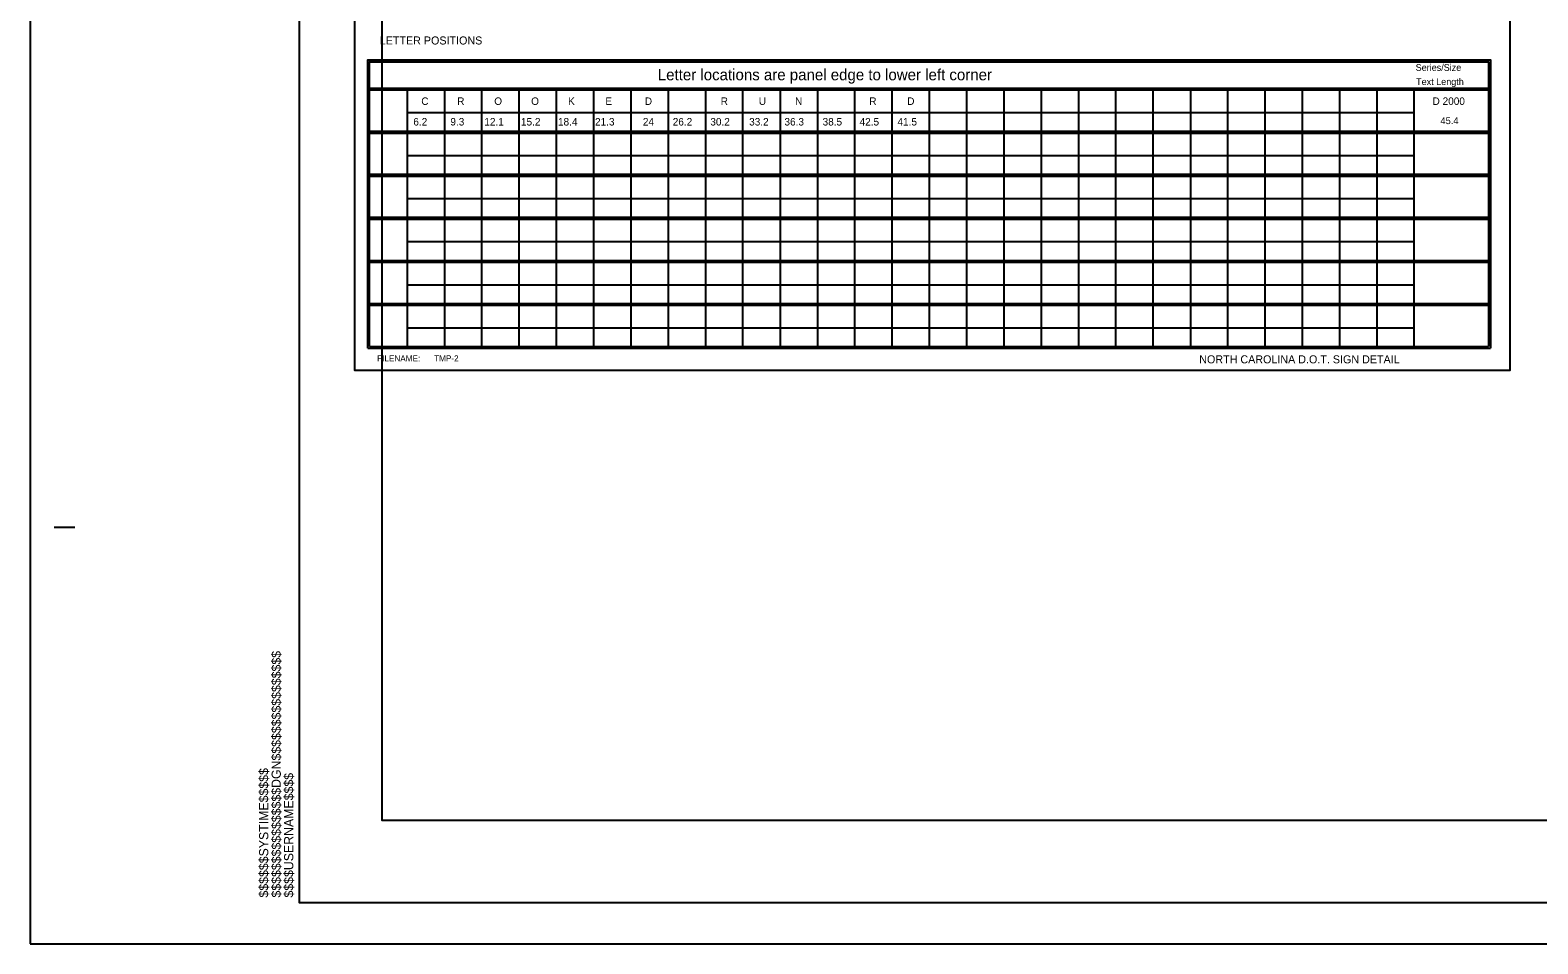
# Model space of a CAD drawing. Extents: x 766449 to 768137, y 650958 to 652521.
# Drawn here: x 766449 to 767363, y 651421 to 651975 of the extents above; entities that cross this region are included whole.
import ezdxf

# ---------------------------------------------------------------- set-up
doc = ezdxf.new("R2010")
doc.units = 0
for name, color, linetype in [('DEV BORDER CELL', 7, 'Continuous'), ('Scratch_Level_0', 7, 'Continuous'), ('Sheet Plot Border Outside CELL', 7, 'Continuous'), ('Text', 7, 'Continuous')]:
    doc.layers.add(name, color=color, linetype=linetype)

msp = doc.modelspace()

# ---------------------------------------------------------------- linework, layer by layer
at = {"layer": 'DEV BORDER CELL'}
for p, q in [((766463.84, 651673.78), (766476.34, 651673.78)), ((766612.34, 651446.28), (766612.34, 651446.28))]:
    msp.add_line(p, q, dxfattribs=at)
msp.add_lwpolyline([(768112.34, 652496.28), (766612.34, 652496.28), (766612.34, 651446.28), (768112.34, 651446.28)], close=True, dxfattribs=at)
at = {"layer": 'Scratch_Level_0'}
msp.add_lwpolyline([(768062.34, 652446.28), (766662.34, 652446.28), (766662.34, 651496.28), (767541.19, 651496.28), (767541.19, 651614.55), (768062.34, 651614.55)], close=True, dxfattribs=at)
at = {"layer": 'Sheet Plot Border Outside CELL'}
msp.add_lwpolyline([(766449.34, 651421.28), (768137.34, 651421.28), (768137.34, 652521.28), (766449.34, 652521.28)], close=True, dxfattribs=at)
at = {"layer": 'Text'}
for p, q in [((766655.01, 651940.06), (767193.2, 651940.06)), ((766655.01, 651938.93), (767193.2, 651938.93)), ((766677.71, 651938.93), (766677.71, 651913.95)), ((766700.4, 651938.93), (766700.4, 651913.95)), ((766722.86, 651938.93), (766722.86, 651913.95)), ((766745.55, 651938.93), (766745.55, 651913.95)), ((766768.01, 651938.93), (766768.01, 651913.95)), ((766790.71, 651938.93), (766790.71, 651913.95)), ((766813.4, 651938.93), (766813.4, 651913.95)), ((766835.86, 651938.93), (766835.86, 651913.95)), ((766858.55, 651938.93), (766858.55, 651913.95)), ((766881.01, 651938.93), (766881.01, 651913.95)), ((766903.71, 651938.93), (766903.71, 651913.95)), ((766926.4, 651938.93), (766926.4, 651913.95)), ((766948.86, 651938.93), (766948.86, 651913.95)), ((766971.55, 651938.93), (766971.55, 651913.95)), ((766994.01, 651938.93), (766994.01, 651913.95)), ((767016.7, 651938.93), (767016.7, 651913.95)), ((767039.4, 651938.93), (767039.4, 651913.95)), ((767061.86, 651938.93), (767061.86, 651913.95)), ((767084.55, 651938.93), (767084.55, 651913.95)), ((767107.01, 651938.93), (767107.01, 651913.95)), ((767129.7, 651938.93), (767129.7, 651913.95)), ((767152.4, 651938.93), (767152.4, 651913.95)), ((767169.11, 651940.06), (767333.01, 651940.06)), ((767169.11, 651938.93), (767333.01, 651938.93)), ((767174.86, 651938.93), (767174.86, 651913.95)), ((767174.86, 651938.93), (767174.86, 651913.95)), ((767197.55, 651938.93), (767197.55, 651913.95)), ((767220.01, 651938.93), (767220.01, 651913.95)), ((767242.7, 651938.93), (767242.7, 651913.95)), ((767265.4, 651938.93), (767265.4, 651913.95)), ((767287.86, 651938.93), (767287.86, 651787.58)), ((766677.71, 651925.3), (767193.2, 651925.3)), ((767169.11, 651925.3), (767287.86, 651925.3)), ((767287.86, 651920.13), (767287.86, 651913.95)), ((766655.01, 651913.95), (767193.2, 651913.95)), ((766655.01, 651912.82), (767193.2, 651912.82)), ((766677.71, 651912.82), (766677.71, 651887.85)), ((766700.4, 651912.82), (766700.4, 651887.85)), ((766722.86, 651912.82), (766722.86, 651887.85)), ((766745.55, 651912.82), (766745.55, 651887.85)), ((766768.01, 651912.82), (766768.01, 651887.85)), ((766790.71, 651912.82), (766790.71, 651887.85)), ((766813.4, 651912.82), (766813.4, 651887.85)), ((766835.86, 651912.82), (766835.86, 651887.85)), ((766858.55, 651912.82), (766858.55, 651887.85)), ((766881.01, 651912.82), (766881.01, 651887.85)), ((766903.71, 651912.82), (766903.71, 651887.85)), ((766926.4, 651912.82), (766926.4, 651887.85)), ((766948.86, 651912.82), (766948.86, 651887.85)), ((766971.55, 651912.82), (766971.55, 651887.85)), ((766994.01, 651912.82), (766994.01, 651887.85)), ((767016.7, 651912.82), (767016.7, 651887.85)), ((767039.4, 651912.82), (767039.4, 651887.85)), ((767061.86, 651912.82), (767061.86, 651887.85)), ((767084.55, 651912.82), (767084.55, 651887.85)), ((767107.01, 651912.82), (767107.01, 651887.85)), ((767129.7, 651912.82), (767129.7, 651887.85)), ((767152.4, 651912.82), (767152.4, 651887.85)), ((767169.11, 651913.95), (767333.01, 651913.95)), ((767169.11, 651912.82), (767333.01, 651912.82)), ((767174.86, 651912.82), (767174.86, 651887.85)), ((767174.86, 651912.82), (767174.86, 651887.85)), ((767197.55, 651912.82), (767197.55, 651887.85)), ((767220.01, 651912.82), (767220.01, 651887.85)), ((767242.7, 651912.82), (767242.7, 651887.85)), ((767265.4, 651912.82), (767265.4, 651887.85)), ((767287.86, 651912.82), (767287.86, 651900.97)), ((766677.71, 651899.2), (767193.2, 651899.2)), ((767169.11, 651899.2), (767287.86, 651899.2)), ((767287.86, 651895.97), (767287.86, 651887.85)), ((766655.01, 651887.85), (767193.2, 651887.85)), ((766655.01, 651886.71), (767193.2, 651886.71)), ((766677.71, 651886.71), (766677.71, 651861.74)), ((766700.4, 651886.71), (766700.4, 651861.74)), ((766722.86, 651886.71), (766722.86, 651861.74)), ((766745.55, 651886.71), (766745.55, 651861.74)), ((766768.01, 651886.71), (766768.01, 651861.74)), ((766790.71, 651886.71), (766790.71, 651861.74)), ((766813.4, 651886.71), (766813.4, 651861.74)), ((766835.86, 651886.71), (766835.86, 651861.74)), ((766858.55, 651886.71), (766858.55, 651861.74)), ((766881.01, 651886.71), (766881.01, 651861.74)), ((766903.71, 651886.71), (766903.71, 651861.74)), ((766926.4, 651886.71), (766926.4, 651861.74)), ((766948.86, 651886.71), (766948.86, 651861.74)), ((766971.55, 651886.71), (766971.55, 651861.74)), ((766994.01, 651886.71), (766994.01, 651861.74)), ((767016.7, 651886.71), (767016.7, 651861.74)), ((767039.4, 651886.71), (767039.4, 651861.74)), ((767061.86, 651886.71), (767061.86, 651861.74)), ((767084.55, 651886.71), (767084.55, 651861.74)), ((767107.01, 651886.71), (767107.01, 651861.74)), ((767129.7, 651886.71), (767129.7, 651861.74)), ((767152.4, 651886.71), (767152.4, 651861.74)), ((767169.11, 651887.85), (767333.01, 651887.85)), ((767169.11, 651886.71), (767333.01, 651886.71)), ((767174.86, 651886.71), (767174.86, 651861.74)), ((767174.86, 651886.71), (767174.86, 651861.74)), ((767197.55, 651886.71), (767197.55, 651861.74)), ((767220.01, 651886.71), (767220.01, 651861.74)), ((767242.7, 651886.71), (767242.7, 651861.74)), ((767265.4, 651886.71), (767265.4, 651861.74)), ((767287.86, 651886.71), (767287.86, 651876.56)), ((766677.71, 651873.09), (767193.2, 651873.09)), ((767169.11, 651873.09), (767287.86, 651873.09)), ((767287.86, 651869.1), (767287.86, 651861.74)), ((766655.01, 651861.74), (767193.2, 651861.74)), ((766655.01, 651860.61), (767193.2, 651860.61)), ((766677.71, 651860.61), (766677.71, 651835.63)), ((766700.4, 651860.61), (766700.4, 651835.63)), ((766722.86, 651860.61), (766722.86, 651835.63)), ((766745.55, 651860.61), (766745.55, 651835.63)), ((766768.01, 651860.61), (766768.01, 651835.63)), ((766790.71, 651860.61), (766790.71, 651835.63)), ((766813.4, 651860.61), (766813.4, 651835.63)), ((766835.86, 651860.61), (766835.86, 651835.63)), ((766858.55, 651860.61), (766858.55, 651835.63)), ((766881.01, 651860.61), (766881.01, 651835.63)), ((766903.71, 651860.61), (766903.71, 651835.63)), ((766926.4, 651860.61), (766926.4, 651835.63)), ((766948.86, 651860.61), (766948.86, 651835.63)), ((766971.55, 651860.61), (766971.55, 651835.63)), ((766994.01, 651860.61), (766994.01, 651835.63)), ((767016.7, 651860.61), (767016.7, 651835.63)), ((767039.4, 651860.61), (767039.4, 651835.63)), ((767061.86, 651860.61), (767061.86, 651835.63)), ((767084.55, 651860.61), (767084.55, 651835.63)), ((767107.01, 651860.61), (767107.01, 651835.63)), ((767129.7, 651860.61), (767129.7, 651835.63)), ((767152.4, 651860.61), (767152.4, 651835.63)), ((767169.11, 651861.74), (767333.01, 651861.74)), ((767169.11, 651860.61), (767333.01, 651860.61)), ((767174.86, 651860.61), (767174.86, 651835.63)), ((767174.86, 651860.61), (767174.86, 651835.63)), ((767197.55, 651860.61), (767197.55, 651835.63)), ((767220.01, 651860.61), (767220.01, 651835.63)), ((767242.7, 651860.61), (767242.7, 651835.63)), ((767265.4, 651860.61), (767265.4, 651835.63)), ((767287.86, 651860.61), (767287.86, 651849.66)), ((766677.71, 651846.98), (767193.2, 651846.98)), ((767169.11, 651846.98), (767287.86, 651846.98)), ((766677.71, 651838.54), (766677.71, 651835.63)), ((766700.4, 651838.54), (766700.4, 651835.63)), ((766722.86, 651838.54), (766722.86, 651835.63)), ((766745.55, 651838.54), (766745.55, 651835.63)), ((766768.01, 651838.54), (766768.01, 651835.63)), ((766790.71, 651838.54), (766790.71, 651835.63)), ((766813.4, 651838.54), (766813.4, 651835.63)), ((766835.86, 651838.54), (766835.86, 651835.63)), ((766858.55, 651838.54), (766858.55, 651835.63)), ((766881.01, 651838.54), (766881.01, 651835.63)), ((766903.71, 651838.54), (766903.71, 651835.63)), ((766926.4, 651838.54), (766926.4, 651835.63)), ((766948.86, 651838.54), (766948.86, 651835.63)), ((766971.55, 651838.54), (766971.55, 651835.63)), ((766994.01, 651838.54), (766994.01, 651835.63)), ((767016.7, 651838.54), (767016.7, 651835.63)), ((767039.4, 651838.54), (767039.4, 651835.63)), ((767061.86, 651838.54), (767061.86, 651835.63)), ((767084.55, 651838.54), (767084.55, 651835.63)), ((767107.01, 651838.54), (767107.01, 651835.63)), ((767129.7, 651838.54), (767129.7, 651835.63)), ((767152.4, 651838.54), (767152.4, 651835.63)), ((767174.86, 651838.54), (767174.86, 651835.63)), ((767174.86, 651838.54), (767174.86, 651835.63)), ((767197.55, 651838.54), (767197.55, 651835.63)), ((767220.01, 651838.54), (767220.01, 651835.63)), ((767242.7, 651838.54), (767242.7, 651835.63)), ((767265.4, 651838.54), (767265.4, 651835.63)), ((767287.86, 651842.19), (767287.86, 651835.63)), ((767287.86, 651838.54), (767287.86, 651835.63)), ((766655.01, 651835.63), (767193.2, 651835.63)), ((766655.01, 651835.63), (767193.2, 651835.63)), ((766655.01, 651834.5), (767193.2, 651834.5)), ((766655.01, 651834.5), (767193.2, 651834.5)), ((766677.71, 651834.5), (766677.71, 651811.16)), ((766677.71, 651834.5), (766677.71, 651809.53)), ((766700.4, 651834.5), (766700.4, 651811.16)), ((766700.4, 651834.5), (766700.4, 651809.53)), ((766722.86, 651834.5), (766722.86, 651811.16)), ((766722.86, 651834.5), (766722.86, 651809.53)), ((766745.55, 651834.5), (766745.55, 651811.16)), ((766745.55, 651834.5), (766745.55, 651809.53)), ((766768.01, 651834.5), (766768.01, 651811.16)), ((766768.01, 651834.5), (766768.01, 651809.53)), ((766790.71, 651834.5), (766790.71, 651811.16)), ((766790.71, 651834.5), (766790.71, 651809.53)), ((766813.4, 651834.5), (766813.4, 651811.16)), ((766813.4, 651834.5), (766813.4, 651809.53)), ((766835.86, 651834.5), (766835.86, 651811.16)), ((766835.86, 651834.5), (766835.86, 651809.53)), ((766858.55, 651834.5), (766858.55, 651811.16)), ((766858.55, 651834.5), (766858.55, 651809.53)), ((766881.01, 651834.5), (766881.01, 651811.16)), ((766881.01, 651834.5), (766881.01, 651809.53)), ((766903.71, 651834.5), (766903.71, 651811.16)), ((766903.71, 651834.5), (766903.71, 651809.53)), ((766926.4, 651834.5), (766926.4, 651811.16)), ((766926.4, 651834.5), (766926.4, 651809.53)), ((766948.86, 651834.5), (766948.86, 651811.16)), ((766948.86, 651834.5), (766948.86, 651809.53)), ((766971.55, 651834.5), (766971.55, 651811.16)), ((766971.55, 651834.5), (766971.55, 651809.53)), ((766994.01, 651834.5), (766994.01, 651811.16)), ((766994.01, 651834.5), (766994.01, 651809.53)), ((767016.7, 651834.5), (767016.7, 651811.16)), ((767016.7, 651834.5), (767016.7, 651809.53)), ((767039.4, 651834.5), (767039.4, 651811.16)), ((767039.4, 651834.5), (767039.4, 651809.53)), ((767061.86, 651834.5), (767061.86, 651811.16)), ((767061.86, 651834.5), (767061.86, 651809.53)), ((767084.55, 651834.5), (767084.55, 651811.16)), ((767084.55, 651834.5), (767084.55, 651809.53)), ((767107.01, 651834.5), (767107.01, 651811.16)), ((767107.01, 651834.5), (767107.01, 651809.53)), ((767129.7, 651834.5), (767129.7, 651811.16)), ((767129.7, 651834.5), (767129.7, 651809.53)), ((767152.4, 651834.5), (767152.4, 651811.16)), ((767152.4, 651834.5), (767152.4, 651809.53)), ((767169.11, 651835.63), (767333.01, 651835.63)), ((767169.11, 651835.63), (767333.01, 651835.63)), ((767169.11, 651834.5), (767333.01, 651834.5)), ((767169.11, 651834.5), (767333.01, 651834.5)), ((767174.86, 651834.5), (767174.86, 651811.16)), ((767174.86, 651834.5), (767174.86, 651809.53)), ((767174.86, 651834.5), (767174.86, 651811.16)), ((767174.86, 651834.5), (767174.86, 651809.53)), ((767197.55, 651834.5), (767197.55, 651811.16)), ((767197.55, 651834.5), (767197.55, 651809.53)), ((767220.01, 651834.5), (767220.01, 651811.16)), ((767220.01, 651834.5), (767220.01, 651809.53)), ((767242.7, 651834.5), (767242.7, 651811.16)), ((767242.7, 651834.5), (767242.7, 651809.53)), ((767265.4, 651834.5), (767265.4, 651811.16)), ((767265.4, 651834.5), (767265.4, 651809.53)), ((767287.86, 651834.5), (767287.86, 651823.26)), ((767287.86, 651834.5), (767287.86, 651823.26)), ((766677.71, 651820.88), (767193.2, 651820.88)), ((766677.71, 651820.88), (767193.2, 651820.88)), ((767169.11, 651820.88), (767287.86, 651820.88)), ((767169.11, 651820.88), (767281.98, 651820.88)), ((766677.71, 651812.43), (766677.71, 651809.53)), ((766700.4, 651812.43), (766700.4, 651809.53)), ((766722.86, 651812.43), (766722.86, 651809.53)), ((766745.55, 651812.43), (766745.55, 651809.53)), ((766768.01, 651812.43), (766768.01, 651809.53)), ((766790.71, 651812.43), (766790.71, 651809.53)), ((766813.4, 651812.43), (766813.4, 651809.53)), ((766835.86, 651812.43), (766835.86, 651809.53)), ((766858.55, 651812.43), (766858.55, 651809.53)), ((766881.01, 651812.43), (766881.01, 651809.53)), ((766903.71, 651812.43), (766903.71, 651809.53)), ((766926.4, 651812.43), (766926.4, 651809.53)), ((766948.86, 651812.43), (766948.86, 651809.53)), ((766971.55, 651812.43), (766971.55, 651809.53)), ((766994.01, 651812.43), (766994.01, 651809.53)), ((767016.7, 651812.43), (767016.7, 651809.53)), ((767039.4, 651812.43), (767039.4, 651809.53)), ((767061.86, 651812.43), (767061.86, 651809.53)), ((767084.55, 651812.43), (767084.55, 651809.53)), ((767107.01, 651812.43), (767107.01, 651809.53)), ((767129.7, 651812.43), (767129.7, 651809.53)), ((767152.4, 651812.43), (767152.4, 651809.53)), ((767174.86, 651812.43), (767174.86, 651809.53)), ((767174.86, 651812.43), (767174.86, 651809.53)), ((767197.55, 651812.43), (767197.55, 651809.53)), ((767220.01, 651812.43), (767220.01, 651809.53)), ((767242.7, 651812.43), (767242.7, 651809.53)), ((767265.4, 651812.43), (767265.4, 651809.53)), ((767287.86, 651816.79), (767287.86, 651811.16)), ((767287.86, 651816.79), (767287.86, 651809.53)), ((767287.86, 651812.43), (767287.86, 651809.53)), ((766655.01, 651809.53), (767193.2, 651809.53)), ((766655.01, 651809.53), (767193.2, 651809.53)), ((766655.01, 651808.39), (767193.2, 651808.39)), ((766655.01, 651808.39), (767193.2, 651808.39)), ((766677.71, 651808.39), (766677.71, 651783.42)), ((766677.71, 651808.39), (766677.71, 651783.42)), ((766700.4, 651808.39), (766700.4, 651783.42)), ((766700.4, 651808.39), (766700.4, 651783.42)), ((766722.86, 651808.39), (766722.86, 651783.42)), ((766722.86, 651808.39), (766722.86, 651783.42)), ((766745.55, 651808.39), (766745.55, 651783.42)), ((766745.55, 651808.39), (766745.55, 651783.42)), ((766768.01, 651808.39), (766768.01, 651783.42)), ((766768.01, 651808.39), (766768.01, 651783.42)), ((766790.71, 651808.39), (766790.71, 651783.42)), ((766790.71, 651808.39), (766790.71, 651783.42)), ((766813.4, 651808.39), (766813.4, 651783.42)), ((766813.4, 651808.39), (766813.4, 651783.42)), ((766835.86, 651808.39), (766835.86, 651783.42)), ((766835.86, 651808.39), (766835.86, 651783.42)), ((766858.55, 651808.39), (766858.55, 651783.42)), ((766858.55, 651808.39), (766858.55, 651783.42)), ((766881.01, 651808.39), (766881.01, 651783.42)), ((766881.01, 651808.39), (766881.01, 651783.42)), ((766903.71, 651808.39), (766903.71, 651783.42)), ((766903.71, 651808.39), (766903.71, 651783.42)), ((766926.4, 651808.39), (766926.4, 651783.42)), ((766926.4, 651808.39), (766926.4, 651783.42)), ((766948.86, 651808.39), (766948.86, 651783.42)), ((766948.86, 651808.39), (766948.86, 651783.42)), ((766971.55, 651808.39), (766971.55, 651783.42)), ((766971.55, 651808.39), (766971.55, 651783.42)), ((766994.01, 651808.39), (766994.01, 651783.42)), ((766994.01, 651808.39), (766994.01, 651783.42)), ((767016.7, 651808.39), (767016.7, 651783.42)), ((767016.7, 651808.39), (767016.7, 651783.42)), ((767039.4, 651808.39), (767039.4, 651783.42)), ((767039.4, 651808.39), (767039.4, 651783.42)), ((767061.86, 651808.39), (767061.86, 651783.42)), ((767061.86, 651808.39), (767061.86, 651783.42)), ((767084.55, 651808.39), (767084.55, 651783.42)), ((767084.55, 651808.39), (767084.55, 651783.42)), ((767107.01, 651808.39), (767107.01, 651783.42)), ((767107.01, 651808.39), (767107.01, 651783.42)), ((767129.7, 651808.39), (767129.7, 651783.42)), ((767129.7, 651808.39), (767129.7, 651783.42)), ((767152.4, 651808.39), (767152.4, 651783.42)), ((767152.4, 651808.39), (767152.4, 651783.42)), ((767169.11, 651809.53), (767333.01, 651809.53)), ((767169.11, 651809.53), (767333.01, 651809.53)), ((767169.11, 651808.39), (767333.01, 651808.39)), ((767169.11, 651808.39), (767333.01, 651808.39)), ((767174.86, 651808.39), (767174.86, 651783.42)), ((767174.86, 651808.39), (767174.86, 651783.42)), ((767174.86, 651808.39), (767174.86, 651783.42)), ((767174.86, 651808.39), (767174.86, 651783.42)), ((767197.55, 651808.39), (767197.55, 651783.42)), ((767197.55, 651808.39), (767197.55, 651783.42)), ((767220.01, 651808.39), (767220.01, 651783.42)), ((767220.01, 651808.39), (767220.01, 651783.42)), ((767242.7, 651808.39), (767242.7, 651783.42)), ((767242.7, 651808.39), (767242.7, 651783.42)), ((767265.4, 651808.39), (767265.4, 651783.42)), ((767265.4, 651808.39), (767265.4, 651783.42)), ((767287.86, 651808.39), (767287.86, 651797.88)), ((767287.86, 651808.39), (767287.86, 651797.88)), ((766677.71, 651794.77), (767193.2, 651794.77)), ((766677.71, 651794.77), (767193.2, 651794.77)), ((767169.11, 651794.77), (767287.86, 651794.77)), ((767169.11, 651794.77), (767283.5, 651794.77)), ((766653.86, 651782.29), (767193.2, 651782.29)), ((766655.01, 651783.42), (767193.2, 651783.42)), ((766655.01, 651783.42), (767193.2, 651783.42)), ((766655.01, 651782.29), (767193.2, 651782.29)), ((767169.11, 651783.42), (767333.01, 651783.42)), ((767169.11, 651783.42), (767333.01, 651783.42)), ((767169.11, 651782.29), (767334.17, 651782.29)), ((767169.11, 651782.29), (767333.01, 651782.29)), ((767287.86, 651789.91), (767287.86, 651783.42)), ((767287.86, 651789.91), (767287.86, 651783.42))]:
    msp.add_line(p, q, dxfattribs=at)
msp.add_lwpolyline([(766646.04, 652254.24), (767346.04, 652254.24), (767346.04, 651768.77), (766646.04, 651768.77)], close=True, dxfattribs=at)
for points in [[(766653.86, 651811.16), (766653.86, 651957.09), (767193.2, 651957.09)], [(766655.01, 651811.16), (766655.01, 651955.95), (767193.2, 651955.95)], [(767169.11, 651957.09), (767334.17, 651957.09), (767334.17, 651811.16)], [(767169.11, 651955.95), (767333.01, 651955.95), (767333.01, 651811.16)], [(766653.86, 651782.29), (766653.86, 651838.54)], [(766655.01, 651783.42), (766655.01, 651838.54)], [(767333.01, 651838.54), (767333.01, 651783.42)], [(767334.17, 651838.54), (767334.17, 651782.29)]]:
    msp.add_lwpolyline(points, dxfattribs=at)

# ---------------------------------------------------------------- texts
at = {"layer": 'DEV BORDER CELL'}
for s, p in [('$$$$$$$$$$$$$$$$DGN$$$$$$$$$$$$$$$$', (766601.22, 651449.36)), ('$$$$$$SYSTIME$$$$$', (766593.64, 651449.36)), ('$$$$USERNAME$$$$', (766608.81, 651449.36))]:
    msp.add_text(s, height=5.584, rotation=90, dxfattribs=at).set_placement(p)
at = {"layer": 'Text'}
for s, height, p in [('LETTER POSITIONS', 4.8646, (766661.16, 651966.48)), ('Letter locations are panel edge to lower left corner', 6.8105, (766829.66, 651944.78)), ('Series/Size', 4.0863, (767288.88, 651950.48)), ('Text Length', 4.0863, (767289.18, 651941.88)), ('FILENAME:', 3.7, (766659.6, 651774.35)), ('TMP-2', 3.7, (766694.12, 651774.35)), ('NORTH CAROLINA D.O.T. SIGN DETAIL', 4.8646, (767157.74, 651773.19))]:
    msp.add_text(s, height=height, rotation=360, dxfattribs=at).set_placement(p)
for s, height, p in [('C', 4.54, (766686.35, 651929.85)), ('R', 4.54, (766708.1, 651929.85)), ('O', 4.54, (766730.56, 651929.85)), ('O', 4.54, (766752.93, 651929.85)), ('K', 4.54, (766775.29, 651929.85)), ('E', 4.54, (766797.89, 651929.85)), ('D', 4.54, (766821.8, 651929.85)), ('R', 4.54, (766867.77, 651929.85)), ('U', 4.54, (766890.85, 651929.85)), ('N', 4.54, (766912.83, 651929.85)), ('R', 4.54, (766957.82, 651929.85)), ('D', 4.54, (766980.8, 651929.85)), ('D 2000', 4.54, (767299.14, 651929.85)), ('6.2', 4.54, (766681.53, 651917.36)), ('9.3', 4.54, (766703.97, 651917.36)), ('12.1', 4.54, (766724.55, 651917.36)), ('15.2', 4.54, (766746.75, 651917.36)), ('18.4', 4.54, (766769.18, 651917.36)), ('21.3', 4.54, (766791.62, 651917.36)), ('24', 4.54, (766820.62, 651917.36)), ('26.2', 4.54, (766838.71, 651917.36)), ('30.2', 4.54, (766861.49, 651917.36)), ('33.2', 4.54, (766885.01, 651917.36)), ('36.3', 4.54, (766906.41, 651917.36)), ('38.5', 4.54, (766929.52, 651917.36)), ('42.5', 4.54, (766951.94, 651917.36)), ('41.5', 4.54, (766974.89, 651917.36)), ('45.4', 4.195, (767303.93, 651918.2))]:
    msp.add_text(s, height=height, dxfattribs=at).set_placement(p)

doc.saveas('drawing.dxf')
